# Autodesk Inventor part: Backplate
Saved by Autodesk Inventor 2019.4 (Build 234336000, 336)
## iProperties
Created: 2020-04
Part Number: Backplate
Material: Generic
Document SubType Name: Modeling
Designer: Administrator
Density: 1 g/cm^3
Appearance: Default
Title: Backplate v2
Author: Administrator
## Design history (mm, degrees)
feature "Body1"
body "Solid1"
